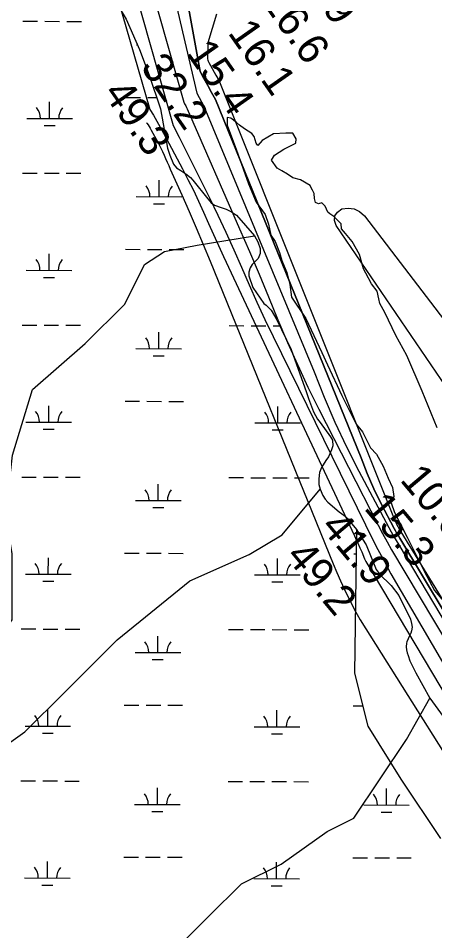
# Model space of a CAD drawing. Extents: x 3161615 to 3199515, y 867541 to 892976.
# Drawn here: x 3179751 to 3180664, y 880456 to 882454 of the extents above; entities that cross this region are included whole.
import ezdxf

# ---------------------------------------------------------------- set-up
doc = ezdxf.new("R2010")
doc.units = 0
for name, color, linetype in [('V-RIVR-EDGE', 7, 'Continuous'), ('V-RIVR-RANG', 7, 'Continuous'), ('V-SITE-VEGE', 7, 'Continuous'), ('V-TOPO-DPTH', 7, 'Continuous'), ('V-TOPO-MAJR', 7, 'Continuous'), ('V-TOPO-MINR', 7, 'Continuous'), ('V-TOPO-SHOR', 7, 'Continuous'), ('V-WETL-SWMP', 7, 'Continuous')]:
    doc.layers.add(name, color=color, linetype=linetype)

msp = doc.modelspace()

# ---------------------------------------------------------------- linework, layer by layer
at = {"layer": 'V-RIVR-EDGE'}
for points in [[(3180668.9, 881557.1), (3180636.2, 881637.3), (3180602.6, 881715.6), (3180578.3, 881759.5), (3180554.1, 881809.6), (3180543.2, 881829.7), (3180540.9, 881839.7), (3180537.6, 881856.4), (3180524.7, 881872.7), (3180512.9, 881896.1), (3180507.2, 881905.6), (3180499.1, 881936.6), (3180482.5, 881965.3), (3180467.8, 881982.5), (3180459.2, 881993), (3180458.3, 882003.5), (3180442.6, 882019.7), (3180434, 882026), (3180429.7, 882029.3), (3180423.6, 882042.7), (3180416, 882049.9), (3180408.8, 882047.5), (3180402.1, 882050.8), (3180400.3, 882059), (3180399.8, 882069.9), (3180395.5, 882077.6), (3180392.7, 882082.3), (3180390.8, 882088.1), (3180369.8, 882100.5), (3180352.7, 882104.8), (3180341.3, 882112.5), (3180328.9, 882119.7), (3180318.4, 882125.9), (3180306, 882143.1), (3180312.7, 882154.5), (3180333.3, 882167.4), (3180359.5, 882180.7), (3180360, 882189.7), (3180352.4, 882202.6), (3180337.7, 882202.6), (3180310.5, 882200.8), (3180285.6, 882186.6), (3180276.1, 882175.1), (3180272.3, 882180.4), (3180268, 882194.7), (3180262.8, 882201.4), (3180247.1, 882211.5), (3180236.1, 882219.6), (3180229.5, 882225.8), (3180217.1, 882235.4), (3180209, 882236.3), (3180208.5, 882220.1), (3180228.8, 882167.6), (3180255.4, 882091.7), (3180272.4, 882051.2), (3180292.4, 882023.9), (3180299.5, 882003.4), (3180304.7, 881979.1), (3180314.2, 881965.2), (3180323.7, 881940.9), (3180328.9, 881923.2), (3180339.8, 881897), (3180345.9, 881871.2), (3180349.6, 881843.5), (3180381, 881796.2), (3180416.1, 881721.8), (3180428.4, 881695), (3180460.2, 881627.7), (3180491.5, 881565.2)], [(3180491.5, 881565.2), (3180505.3, 881548.4), (3180522.9, 881513.1), (3180536.2, 881499.2), (3180550.9, 881473.5), (3180561.4, 881446.7), (3180570.8, 881426.2), (3180574.1, 881406.6), (3180567.9, 881392.8), (3180575.5, 881371.8), (3180603, 881317.9), (3180641, 881241.9), (3180662.8, 881200.9), (3180679, 881181.8)]]:
    msp.add_lwpolyline(points, dxfattribs=at)
at = {"layer": 'V-SITE-VEGE'}
for points in [[(3179938.1, 882535.7), (3179987.5, 882452.2), (3180017.1, 882385.5), (3180037.7, 882329.2), (3180062.9, 882255.6), (3180078.2, 882169.2), (3180083.3, 882154.2), (3180091.3, 882134.3), (3180097.9, 882126.1), (3180107.1, 882120.6), (3180118.6, 882113.1), (3180128.6, 882104.9), (3180133.7, 882099.6), (3180166.8, 882058.5), (3180173.9, 882050), (3180181.1, 882045), (3180195.8, 882039.5), (3180206.5, 882036.2), (3180218.2, 882030.2), (3180229.1, 882022.5), (3180268.4, 881977.4), (3180276.4, 881964.4), (3180281.3, 881950), (3180281.3, 881939), (3180276.7, 881928.1), (3180271.2, 881921.8), (3180263.7, 881914.4), (3180259.2, 881907.2), (3180256.2, 881898), (3180256, 881890), (3180265.4, 881864.3), (3180289, 881829.6), (3180294.5, 881825.4), (3180305.4, 881815), (3180317.5, 881793.4), (3180349.3, 881728.4), (3180382.6, 881634.2), (3180386.8, 881621)], [(3180386.8, 881621), (3180398.2, 881591.8), (3180406.9, 881576.2), (3180412.9, 881568.5), (3180434.9, 881537.3), (3180439.9, 881529.8), (3180440.4, 881517.4), (3180437.4, 881508.6), (3180434.1, 881500.5), (3180430.8, 881493.5), (3180424.8, 881485.3), (3180415.3, 881470.3), (3180410.8, 881459.6), (3180409.6, 881445.7), (3180409.6, 881433.3), (3180412.8, 881422.8), (3180418.4, 881409.1), (3180423.7, 881400.8), (3180429.3, 881394.4), (3180454.4, 881373.2), (3180459.7, 881369.7), (3180467.4, 881363.4), (3180472.9, 881357.6), (3180474.6, 881355.9), (3180492, 881334.7), (3180505.6, 881313.6), (3180513.6, 881300.8), (3180535.3, 881247.2), (3180543.8, 881235.5), (3180550.7, 881228.5), (3180559.6, 881220.8), (3180568.3, 881211.8), (3180585.2, 881189.7), (3180610.3, 881138.5), (3180612.9, 881128.4), (3180614, 881120.3), (3180612.9, 881112.9), (3180611.4, 881107.5), (3180608.5, 881102), (3180602.4, 881088.6), (3180601.7, 881085.3), (3180601.1, 881077.6), (3180601.6, 881071.1), (3180603.3, 881064.6), (3180605.3, 881058.9), (3180609.1, 881046.9), (3180622.2, 881021), (3180652.6, 880964.9), (3180681.8, 880925)]]:
    msp.add_lwpolyline(points, dxfattribs=at)
at = {"layer": 'V-TOPO-DPTH'}
msp.add_lwpolyline([(3181085.8, 880486.9), (3180587.4, 881315.3), (3180584, 881320.5), (3180580.6, 881325.9), (3180577.5, 881331.3), (3180574.5, 881336.8), (3180546.3, 881390.8), (3180530.2, 881423.7), (3180515.4, 881457.2), (3180502.5, 881491.4), (3180183.4, 882276.3), (3180174.9, 882291.5), (3180166.4, 882306.7), (3180158, 882322), (3180149.6, 882337.3), (3180121.7, 882489.6)], dxfattribs=at)
at = {"layer": 'V-TOPO-MAJR'}
msp.add_lwpolyline([(3179821.7, 883165.5), (3180090.4, 882219), (3180103.4, 882193.5), (3180170, 882060.5), (3180188.4, 882023), (3180206.3, 881985.3), (3180223.4, 881947.2), (3180240.1, 881908.9), (3180256.8, 881870.6), (3180273.8, 881832.5), (3180291.5, 881794.6), (3180309.6, 881757), (3180511.8, 881344.6), (3180525.3, 881317.6), (3180539.1, 881290.8), (3180553.3, 881264.1), (3180567.7, 881237.6), (3180952.3, 880580)], dxfattribs=at)
at = {"layer": 'V-TOPO-MINR'}
for points in [[(3179922.2, 883234.4), (3180142.2, 882289.8), (3180157.7, 882261.5), (3180399.8, 881680), (3180421.6, 881624.4), (3180444.8, 881569.4), (3180470.2, 881515.5), (3180497.2, 881462.2), (3180562.8, 881339), (3180568.1, 881329.4), (3180573.5, 881319.8), (3180579.1, 881310.4), (3180584.9, 881301), (3181084.4, 880460.7)], [(3179841.6, 883229.2), (3180113.9, 882270), (3180115.6, 882266.7), (3180116.7, 882264.6), (3180118, 882262.1), (3180119.8, 882258.2), (3180121, 882255.6), (3180236.2, 881992.5), (3180257.6, 881943), (3180278.8, 881893.4), (3180299.5, 881843.7), (3180320.1, 881793.8), (3180341, 881744.1), (3180385.9, 881646.2), (3180409.9, 881597.9), (3180540, 881343.9), (3180549.5, 881325.7), (3180559.2, 881307.7), (3180569.2, 881289.9), (3181066.7, 880456.3)], [(3179770.2, 883186), (3180039.6, 882254.3), (3180047.4, 882241.5), (3180054.9, 882228.7), (3180062.2, 882215.7), (3180069.4, 882202.6), (3180110.8, 882124.6), (3180123, 882101), (3180134.8, 882077.3), (3180146.1, 882053.2), (3180157, 882029), (3180167.8, 882004.7), (3180178.6, 881980.5), (3180189.7, 881956.4), (3180200.9, 881932.3), (3180487.7, 881321), (3180491.8, 881312.2), (3180495.8, 881303.3), (3180499.7, 881294.4), (3180503.6, 881285.5), (3180509.9, 881270.3), (3180511.7, 881266.1), (3180512.3, 881264.8), (3181017.4, 880416.9)], [(3180121.7, 882489.6), (3180149.6, 882337.3), (3180158, 882322), (3180166.4, 882306.7), (3180174.9, 882291.5), (3180183.4, 882276.3), (3180502.5, 881491.4), (3180515.4, 881457.2), (3180530.2, 881423.7), (3180546.3, 881390.8), (3180574.5, 881336.8), (3180577.5, 881331.3), (3180580.6, 881325.9), (3180584, 881320.5), (3180587.4, 881315.3), (3181085.8, 880486.9)], [(3180185.4, 882462.8), (3180166.5, 882399.8), (3180165.9, 882364.9), (3180166.6, 882362.3), (3180167.6, 882359.7), (3180168.7, 882357.3), (3180184.3, 882329), (3180186.2, 882325.5), (3180188.2, 882322), (3180190.2, 882318.5), (3180192.2, 882315), (3180573.6, 881361.6), (3180576.6, 881354), (3180580, 881346.5), (3180586.1, 881334.6), (3180586.8, 881333.2), (3180589.4, 881329.1), (3181117.4, 880470.4)], [(3180032.4, 882224.9), (3180033.2, 882224.4), (3180035.7, 882220.7), (3180038.1, 882216.9), (3180040.4, 882213), (3180042.6, 882209.1), (3180056, 882184.3), (3180059.9, 882176.9), (3180063.7, 882169.4), (3180067.2, 882161.9), (3180070.7, 882154.2), (3180074, 882146.6), (3180077.4, 882138.9), (3180080.8, 882131.3), (3180084.2, 882123.6), (3180109.6, 882067.1), (3180125.5, 882031.1), (3180141.2, 881995), (3180156.5, 881958.7), (3180171.5, 881922.3), (3180441, 881259.5), (3180449, 881240.6), (3180457.2, 881221.9), (3180465.8, 881203.4), (3180474.7, 881185), (3180481, 881172.3), (3180487.1, 881160.4), (3180493.4, 881148.6), (3180499.9, 881137), (3180797.2, 880665.5)], [(3180765.1, 881534.3), (3180447.5, 881999.8), (3180444.1, 882011.1), (3180444.5, 882021.2), (3180450.3, 882029.5), (3180459.8, 882036.6), (3180474, 882038.4), (3180487.2, 882037), (3180498.9, 882030.8), (3180509.7, 882021.4), (3180829.8, 881603.1)]]:
    msp.add_lwpolyline(points, dxfattribs=at)
at = {"layer": 'V-TOPO-SHOR'}
for points in [[(3179677.5, 881053.4), (3179737.7, 881136.8), (3179738.1, 881280.9), (3179723.9, 881367.5), (3179738.7, 881497.2), (3179782.3, 881641.2), (3179897.9, 881741.8), (3179984.6, 881828), (3180028.1, 881914.4), (3180071.4, 881943.1), (3180143.5, 881957.3), (3180268.4, 881977.4)], [(3179218.5, 880225.5), (3179403.9, 880344.9), (3179461.9, 880474.5), (3179534.5, 880632.9), (3179621.3, 880776.8), (3179664.7, 880819.9), (3179765.8, 880891.7), (3179852.5, 880977.9), (3179968.2, 881092.9), (3180127.1, 881222.2), (3180257, 881279.5), (3180329.2, 881322.6), (3180412.8, 881422.8)], [(3180486, 880702.3), (3180601.8, 880875), (3180652.6, 880964.9)], [(3179011.2, 879077.5), (3179069.2, 879192.7), (3179112.7, 879293.5), (3179156.2, 879379.8), (3179300.9, 879581.2), (3179330.1, 879725.3), (3179460.2, 879854.7), (3179503.7, 879926.6), (3179532.7, 880013), (3179677.1, 880099.1), (3179749.4, 880156.6), (3179893.7, 880228.3), (3180052.7, 880372), (3180168.3, 880487), (3180240.6, 880558.8), (3180327.2, 880601.8), (3180428.3, 880673.6), (3180486, 880702.3)]]:
    msp.add_lwpolyline(points, dxfattribs=at)
at = {"layer": 'V-WETL-SWMP'}
for p, q in [((3179761.5, 882447.5), (3179793.5, 882447.4)), ((3179809.5, 882447.3), (3179841.5, 882447.2)), ((3179857.5, 882447.2), (3179889.5, 882447.1)), ((3180010.6, 882396), (3180012.4, 882396)), ((3179986.9, 882280.7), (3180018.9, 882280.6)), ((3180034.9, 882280.5), (3180054.4, 882280.5)), ((3179819.7, 882234.7), (3179819.8, 882270.7)), ((3179769.7, 882234.8), (3179869.7, 882234.5)), ((3179807.7, 882219.3), (3179831.7, 882219.2)), ((3179760.5, 882114.8), (3179792.5, 882114.7)), ((3179808.5, 882114.6), (3179840.5, 882114.6)), ((3179856.5, 882114.5), (3179888.5, 882114.4)), ((3180059.7, 882063.2), (3180059.8, 882099.2)), ((3180009.7, 882063.3), (3180109.7, 882063.1)), ((3180047.7, 882047.8), (3180071.7, 882047.7)), ((3179818.8, 881902), (3179818.9, 881938)), ((3179986, 881948), (3180018, 881947.9)), ((3180034, 881947.8), (3180066, 881947.8)), ((3180082, 881947.7), (3180114, 881947.6)), ((3179768.8, 881902.2), (3179868.8, 881901.9)), ((3179806.8, 881886.6), (3179830.8, 881886.5)), ((3179759.6, 881782.1), (3179791.6, 881782)), ((3179807.6, 881782), (3179839.6, 881781.9)), ((3179855.6, 881781.8), (3179887.6, 881781.8)), ((3180213.5, 881780.9), (3180245.5, 881780.8)), ((3180261.5, 881780.7), (3180293.5, 881780.6)), ((3180309.5, 881780.6), (3180323.8, 881780.5)), ((3180058.8, 881730.5), (3180058.9, 881766.5)), ((3180008.8, 881730.7), (3180108.8, 881730.4)), ((3180046.8, 881715.1), (3180070.8, 881715.1)), ((3179985.1, 881615.3), (3180017.1, 881615.2)), ((3180033.1, 881615.2), (3180065.1, 881615.1)), ((3180081.1, 881615), (3180113.1, 881615)), ((3179817.9, 881569.3), (3179818, 881605.3)), ((3180319.8, 881568), (3180319.9, 881604)), ((3179767.9, 881569.5), (3179867.9, 881569.2)), ((3179805.8, 881553.9), (3179829.8, 881553.9)), ((3180269.8, 881568.1), (3180369.8, 881567.8)), ((3180307.7, 881552.6), (3180331.7, 881552.5)), ((3179758.7, 881449.4), (3179790.7, 881449.3)), ((3179806.7, 881449.3), (3179838.7, 881449.2)), ((3179854.7, 881449.2), (3179886.7, 881449.1)), ((3180057.9, 881397.9), (3180058, 881433.9)), ((3180212.6, 881448.2), (3180244.6, 881448.1)), ((3180260.6, 881448), (3180292.6, 881448)), ((3180308.6, 881447.9), (3180340.6, 881447.8)), ((3180356.6, 881447.8), (3180388.6, 881447.7)), ((3180007.9, 881398), (3180107.9, 881397.7)), ((3180045.8, 881382.5), (3180069.8, 881382.4)), ((3179817, 881236.7), (3179817.1, 881272.7)), ((3179984.2, 881282.6), (3180016.2, 881282.5)), ((3180032.2, 881282.5), (3180064.2, 881282.4)), ((3180080.2, 881282.4), (3180112.2, 881282.3)), ((3180486.1, 881281.2), (3180491.3, 881281.2)), ((3180318.9, 881235.3), (3180319, 881271.3)), ((3179767, 881236.8), (3179867, 881236.5)), ((3180268.9, 881235.4), (3180368.9, 881235.1)), ((3179804.9, 881221.3), (3179828.9, 881221.2)), ((3180306.8, 881219.9), (3180330.8, 881219.8)), ((3179757.8, 881116.8), (3179789.8, 881116.7)), ((3179805.8, 881116.6), (3179837.8, 881116.5)), ((3179853.8, 881116.5), (3179885.8, 881116.4)), ((3180211.7, 881115.5), (3180243.7, 881115.4)), ((3180259.7, 881115.4), (3180291.7, 881115.3)), ((3180307.7, 881115.2), (3180339.7, 881115.1)), ((3180355.7, 881115.1), (3180387.7, 881115)), ((3180057, 881065.2), (3180057.1, 881101.2)), ((3180007, 881065.3), (3180107, 881065.1)), ((3180044.9, 881049.8), (3180068.9, 881049.7)), ((3179816, 880904), (3179816.1, 880940)), ((3179983.2, 880950), (3180015.2, 880949.9)), ((3180031.2, 880949.8), (3180063.2, 880949.7)), ((3180079.2, 880949.7), (3180111.2, 880949.6)), ((3180317.9, 880902.6), (3180318, 880938.6)), ((3180485.1, 880948.6), (3180505.5, 880948.5)), ((3179766, 880904.1), (3179866, 880903.9)), ((3180267.9, 880902.7), (3180367.9, 880902.5)), ((3179804, 880888.6), (3179828, 880888.5)), ((3180305.9, 880887.2), (3180329.9, 880887.1)), ((3179756.9, 880784.1), (3179788.9, 880784)), ((3179804.9, 880784), (3179836.9, 880783.9)), ((3179852.9, 880783.8), (3179884.9, 880783.7)), ((3180210.8, 880782.8), (3180242.8, 880782.7)), ((3180258.8, 880782.7), (3180290.8, 880782.6)), ((3180306.8, 880782.6), (3180338.8, 880782.5)), ((3180354.8, 880782.4), (3180386.8, 880782.3)), ((3180056, 880732.5), (3180056.1, 880768.5)), ((3180557.9, 880731.1), (3180558, 880767.1)), ((3180006, 880732.7), (3180106, 880732.4)), ((3180044, 880717.1), (3180068, 880717.1)), ((3180507.9, 880731.3), (3180607.9, 880731)), ((3180545.9, 880715.7), (3180569.9, 880715.7)), ((3179982.3, 880617.3), (3180014.3, 880617.2)), ((3180030.3, 880617.2), (3180062.3, 880617.1)), ((3180078.3, 880617), (3180110.3, 880616.9)), ((3180484.2, 880615.9), (3180516.2, 880615.8)), ((3180532.2, 880615.8), (3180564.2, 880615.7)), ((3180580.2, 880615.6), (3180612.2, 880615.5)), ((3179815.1, 880571.3), (3179815.2, 880607.3)), ((3180317, 880569.9), (3180317.1, 880605.9)), ((3179765.1, 880571.5), (3179865.1, 880571.2)), ((3179803.1, 880555.9), (3179827.1, 880555.9)), ((3180267, 880570.1), (3180367, 880569.8)), ((3180305, 880554.5), (3180329, 880554.5))]:
    msp.add_line(p, q, dxfattribs=at)
for points in [[(3179938.1, 882535.7), (3179987.5, 882452.2), (3180017.1, 882385.5), (3180037.7, 882329.2), (3180062.9, 882255.6), (3180078.2, 882169.2), (3180083.3, 882154.2), (3180091.3, 882134.3), (3180097.9, 882126.1), (3180107.1, 882120.6), (3180118.6, 882113.1), (3180128.6, 882104.9)], [(3180128.6, 882104.9), (3180133.7, 882099.6), (3180166.8, 882058.5), (3180173.9, 882050), (3180181.1, 882045), (3180195.8, 882039.5), (3180206.5, 882036.2), (3180218.2, 882030.2), (3180229.1, 882022.5), (3180268.4, 881977.4), (3180276.4, 881964.4), (3180281.3, 881950), (3180281.3, 881939), (3180276.7, 881928.1), (3180271.2, 881921.8), (3180263.7, 881914.4), (3180259.2, 881907.2), (3180256.2, 881898), (3180256, 881890), (3180265.4, 881864.3), (3180289, 881829.6), (3180294.5, 881825.4), (3180305.4, 881815), (3180317.5, 881793.4), (3180349.3, 881728.4), (3180382.6, 881634.2), (3180386.8, 881621), (3180398.2, 881591.8), (3180406.9, 881576.2), (3180412.9, 881568.5), (3180434.9, 881537.3), (3180439.9, 881529.8), (3180440.4, 881517.4), (3180437.4, 881508.6), (3180434.1, 881500.5), (3180430.8, 881493.5), (3180424.8, 881485.3), (3180415.3, 881470.3), (3180410.8, 881459.6), (3180409.6, 881445.7), (3180409.6, 881433.3), (3180412.8, 881422.8), (3180418.4, 881409.1), (3180423.7, 881400.8), (3180429.3, 881394.4), (3180454.4, 881373.2), (3180459.7, 881369.7), (3180467.4, 881363.4), (3180474.6, 881355.9), (3180492, 881334.7), (3180487.8, 881019.6), (3180516.7, 880903.8), (3180589.1, 880787.9), (3180675.9, 880657.6)]]:
    msp.add_lwpolyline(points, dxfattribs=at)
for centre, start, end in [((3179764.5, 882235.3), 359.0699, 40.6135), ((3179875, 882235), 139.0699, 180.6135), ((3180004.5, 882063.8), 359.0699, 40.6135), ((3180115, 882063.5), 139.0699, 180.6135), ((3179763.6, 881902.6), 359.0699, 40.6135), ((3179874, 881902.3), 139.0699, 180.6135), ((3180003.6, 881731.2), 359.0699, 40.6135), ((3180114, 881730.9), 139.0699, 180.6135), ((3179762.6, 881570), 359.0699, 40.6135), ((3179873.1, 881569.7), 139.0699, 180.6135), ((3180264.5, 881568.6), 359.0699, 40.6135), ((3180375, 881568.3), 139.0699, 180.6135), ((3180002.6, 881398.5), 359.0699, 40.6135), ((3180113.1, 881398.2), 139.0699, 180.6135), ((3179761.7, 881237.3), 359.0699, 40.6135), ((3179872.2, 881237), 139.0699, 180.6135), ((3180263.6, 881235.9), 359.0699, 40.6135), ((3180374.1, 881235.6), 139.0699, 180.6135), ((3180001.7, 881065.8), 359.0699, 40.6135), ((3180112.2, 881065.5), 139.0699, 180.6135), ((3179760.8, 880904.6), 359.0699, 40.6135), ((3179871.3, 880904.3), 139.0699, 180.6135), ((3180262.7, 880903.2), 359.0699, 40.6135), ((3180373.2, 880902.9), 139.0699, 180.6135), ((3180000.8, 880733.1), 359.0699, 40.6135), ((3180111.3, 880732.8), 139.0699, 180.6135), ((3180502.7, 880731.8), 359.0699, 40.6135), ((3180613.2, 880731.4), 139.0699, 180.6135), ((3179759.9, 880571.9), 359.0699, 40.6135), ((3179870.4, 880571.6), 139.0699, 180.6135), ((3180261.8, 880570.6), 359.0699, 40.6135), ((3180372.3, 880570.3), 139.0699, 180.6135)]:
    msp.add_arc(centre, 35.2, start, end, dxfattribs=at)

# ---------------------------------------------------------------- texts
at = {"layer": 'V-RIVR-RANG'}
for s, rotation, p in [('13.9', 304.8783, (3180344.9, 882577.2)), ('16.6', 305.0581, (3180282.8, 882491)), ('16.1', 305.0581, (3180208.9, 882422.2)), ('15.4', 305.0581, (3180117.9, 882377.8)), ('32.2', 304.8783, (3180017.5, 882347.4)), ('49.3', 304.8783, (3179935.6, 882290.1)), ('10.0', 310.0603, (3180585.5, 881442.4)), ('15.3', 310.0603, (3180506.8, 881380.7)), ('41.9', 309.8983, (3180411.4, 881339.2)), ('49.2', 309.8983, (3180335, 881274.7))]:
    msp.add_text(s, height=67, rotation=rotation, dxfattribs=at).set_placement(p)

doc.saveas('drawing.dxf')
